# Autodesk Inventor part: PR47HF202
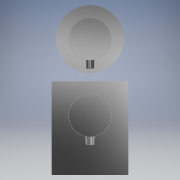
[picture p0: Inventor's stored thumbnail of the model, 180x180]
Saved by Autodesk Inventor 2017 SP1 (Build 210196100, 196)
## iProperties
Created: 2018-11
Part Number: PR47HF202
Material: Generico
Document SubType Name: Modeling
Designer: CIANI A.
Density: 1 g/cm^3
Appearance: Default
Author: CIANI A.
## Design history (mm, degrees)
feature "Base4"
node "Solido1"
node "Solido5"
